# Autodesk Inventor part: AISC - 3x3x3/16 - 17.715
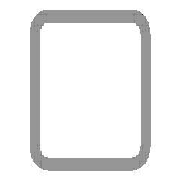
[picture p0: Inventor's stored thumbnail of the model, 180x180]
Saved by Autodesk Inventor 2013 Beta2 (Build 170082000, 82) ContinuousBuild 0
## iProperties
IsCustomPart: 1
Created: 2011-01
Part Number: AISC - 3x3x3/16 - 17.715
Material: Steel, Mild
Description: Tube
Document SubType Name: Modeling
Standard: ANSI
Designer: Beta-8540w
Standards Organization: ANSI
Language: en-US
Size Designation: 3x3x3/16
Categories: <MemberInstance><Categories><Category DisplayName="Structural Shapes" InternalName="089c4875-fa83-4c05-b084-43b9cc11f5ed" Mnemonic="GRDR"><CategoryParameter Dis
Stock Number: 3x3x3/16
Density: 7.86 g/cm^3
G_L: 17.715 in
G_W: 3.000 in
G_H: 3.000 in
_CCFamilyMember: 9
_CCFamilyDisplayName: ANSI AISC (Square) - Tube
_FrameMemberDoc: Frame Member File
_Version: 15.0.0
_GetPNFromCC: 1
Author: Beta-8540w
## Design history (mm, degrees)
node "Start plane"
node "End plane"
sketch "Sketch"
  geometry: L1 (-38.1, -28.575)-(-38.1, 28.575); L2 (-28.575, 38.1)-(28.575, 38.1); L3 (38.1, 28.575)-(38.1, -28.575); L4 (28.575, -38.1)-(-28.575, -38.1); L5 (-28.575, 33.337)-(28.575, 33.338); L6 (33.338, 28.575)-(33.338, -28.575); L7 (28.575, -33.337)-(-28.575, -33.338); L8 (-33.338, -28.575)-(-33.338, 28.575); L9 (0, 56.102)-(0, -56.102) reference; L10 (-56.102, 0)-(56.102, 0) reference; A1 r 9.525 centre (-28.575, -28.575) between (-38.1, -28.575) and (-28.575, -38.1); A2 r 9.525 centre (-28.575, 28.575) between (-28.575, 38.1) and (-38.1, 28.575); A3 r 9.525 centre (28.575, 28.575) between (38.1, 28.575) and (28.575, 38.1); A4 r 9.525 centre (28.575, -28.575) between (28.575, -38.1) and (38.1, -28.575); A5 r 4.763 centre (-28.575, 28.575) between (-28.575, 33.337) and (-33.338, 28.575); A6 r 4.763 centre (28.575, 28.575) between (33.338, 28.575) and (28.575, 33.338); A7 r 4.763 centre (28.575, -28.575) between (28.575, -33.337) and (33.338, -28.575); A8 r 4.763 centre (-28.575, -28.575) between (-33.338, -28.575) and (-28.575, -33.338)
  constraints: 16 end point, 16 point on circle, 8 centre point, 8 tangent, 4 parallel, 3 equal radius, 2 perpendicular, 7 other
  dimensions: "d10" = 76.2 distance between parallel lines of L2 L4 (= G_H); "d11" = 76.2 distance between parallel lines of L1 L3 (= G_W); "d12" = 4.7625 distance between parallel lines of L3 L6 (= G_T); "d15" = 38.1 distance between parallel lines of L2 L10 (= 0.5 x d10); "d16" = 38.1 distance between parallel lines of L9 L3 (= 0.5 x d11); "d17" = 9.525 radius of A1 (= G_IR)
extrude "Body" new body sketch "Sketch" stored distance "d3" = 449.97309 (= G_L); taper "d4" = 0 deg
node "Driven Length"
  sketch "Sketch3"
    geometry: L1 (0, 0)-(10, 0) reference
    constraints: 2 end point, 1 horizontal
  workplane "Work Plane3"
  sketch "Sketch4"
    geometry: L1 (-2, 0)-(12, 0) reference; L2 (-2, 449.973)-(12, 449.973) reference
    dimensions: "d19" = 449.97309 distance between parallel lines of L1 L2 (derived)
body "Solid1"
other parameters: "G_W" = 76.2 [user parameter; used in 1 equation term], "G_H" = 76.2 [user parameter; used in 1 equation term], "G_T" = 4.7625 [user parameter; used in 1 equation term], "G_IR" = 9.525 [user parameter; used in 1 equation term], "G_L" = 449.97309 (= d19) [user parameter; used in 1 equation term], "G_OFFSET_START" = 0 [user parameter; used in 1 equation term], "G_OFFSET_END" = 0 [user parameter; used in 1 equation term], "d13" = 0 (computed from G_OFFSET_START), "d14" = 449.97309 (= G_OFFSET_END + B_L), "B_L" = 449.97309 [user parameter; used in 1 equation term], "d18" = 90 deg
